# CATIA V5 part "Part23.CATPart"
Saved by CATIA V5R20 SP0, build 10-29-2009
Part number: 9FP040612-20130117_2
Revision: ANY
Definition: UNKNOWN
Nomenclature: 9FP040612-20130117_2
Source: Unknown
Bounding box of the stored display mesh (mm): x -6 to 6, y -6 to 6, z 0 to 8
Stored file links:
  C:\Users\Utente\Desktop\IO LAVORO\3D X SITO CF\CUMSA\3D files PF\PF 064200\Part23.CATPart
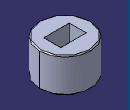
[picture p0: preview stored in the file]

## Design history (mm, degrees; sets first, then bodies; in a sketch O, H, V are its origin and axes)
Body1 "Chaflán1" (main body)
  Solid1: solid without history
